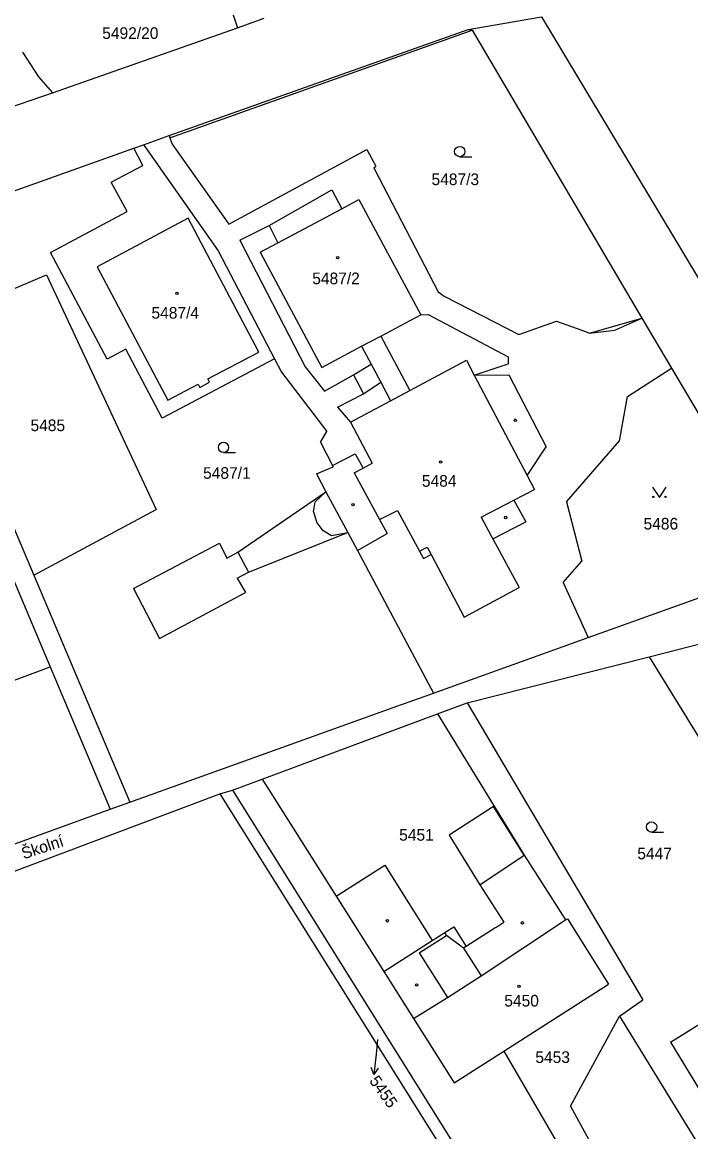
# Model space of a CAD drawing. Extents: x -717507 to -715515, y -957700 to -954941.
# Drawn here: x -716318.3 to -716220.6, y -955452.3 to -955290.3 of the extents above; entities that cross this region are included whole.
import ezdxf

# ---------------------------------------------------------------- set-up
doc = ezdxf.new("R2010")
doc.units = 0
for name, color, linetype in [('Hranice parcel', 7, 'Continuous'), ('Parcelní čísla', 7, 'Continuous'), ('Pop  PČ popisy', 7, 'Continuous'), ('Vnitřní kresba', 7, 'Continuous'), ('Značky budov', 7, 'Continuous'), ('Značky kultur', 7, 'Continuous')]:
    doc.layers.add(name, color=color, linetype=linetype)

msp = doc.modelspace()

# ---------------------------------------------------------------- linework, layer by layer
at = {"layer": 'Hranice parcel'}
for points in [[(-716253.14, -955291.32), (-716242.42, -955289.49)], [(-716242.42, -955289.49), (-716201.66, -955357.42)], [(-716313.88, -955300.58), (-716286.81, -955291.09)], [(-716286.81, -955291.09), (-716282.92, -955289.68)], [(-716296.83, -955306.84), (-716253.14, -955291.32)], [(-716253.14, -955291.32), (-716252.56, -955291.46)], [(-716252.56, -955291.46), (-716227.73, -955333.49)], [(-716318.24, -955294.63), (-716315.92, -955298.25)], [(-716315.92, -955298.25), (-716313.88, -955300.58)], [(-716320.4, -955302.84), (-716313.88, -955300.58)], [(-716300.57, -955308.17), (-716296.83, -955306.84)], [(-716296.83, -955306.84), (-716296.71, -955307.15)], [(-716296.71, -955307.15), (-716296.37, -955308.09)], [(-716337.65, -955321.38), (-716302, -955308.68)], [(-716302, -955308.68), (-716300.57, -955308.17)], [(-716300.67, -955311.21), (-716302, -955308.68)], [(-716300.57, -955308.17), (-716300.38, -955308.43)], [(-716300.38, -955308.43), (-716289.68, -955323.69)], [(-716296.37, -955308.09), (-716288.11, -955319.76)], [(-716288.11, -955319.76), (-716267.94, -955308.86)], [(-716267.94, -955308.86), (-716266.61, -955311.32)], [(-716305.28, -955313.62), (-716300.67, -955311.21)], [(-716266.92, -955311.56), (-716266.61, -955311.32)], [(-716266.92, -955311.56), (-716257.49, -955329.66)], [(-716302.97, -955317.94), (-716305.28, -955313.62)], [(-716282.22, -955319.95), (-716273.05, -955314.77)], [(-716273.05, -955314.77), (-716271.58, -955317.52)], [(-716271.58, -955317.52), (-716269.09, -955316.19)], [(-716269.09, -955316.19), (-716260.05, -955333.01)], [(-716314.14, -955323.91), (-716302.97, -955317.94)], [(-716282.22, -955319.95), (-716280.94, -955322.51)], [(-716283.5, -955323.87), (-716280.94, -955322.51)], [(-716305.87, -955339.49), (-716314.14, -955323.91)], [(-716289.68, -955323.69), (-716281.41, -955339.42)], [(-716283.5, -955323.87), (-716274.53, -955340.71)], [(-716332.07, -955334.52), (-716314.74, -955327.19)], [(-716314.74, -955327.19), (-716298.71, -955361.45)], [(-716337.22, -955329.83), (-716314.22, -955384.44)], [(-716257.49, -955329.66), (-716256.65, -955330.3)], [(-716256.65, -955330.3), (-716245.71, -955335.87)], [(-716265.88, -955336.12), (-716260.05, -955333.01)], [(-716332.07, -955334.52), (-716316.6, -955371.03)], [(-716245.71, -955335.87), (-716240.24, -955333.92)], [(-716240.24, -955333.92), (-716235.96, -955335.46)], [(-716235.39, -955335.67), (-716227.73, -955333.49)], [(-716227.73, -955333.49), (-716223.4, -955340.81)], [(-716265.88, -955336.12), (-716261.65, -955344.05)], [(-716235.96, -955335.46), (-716235.39, -955335.67)], [(-716303.16, -955338.02), (-716305.87, -955339.49)], [(-716297.84, -955348.12), (-716303.16, -955338.02)], [(-716274.53, -955340.71), (-716268.69, -955337.6)], [(-716268.69, -955337.6), (-716267.3, -955340.22)], [(-716281.41, -955339.42), (-716297.84, -955348.12)], [(-716281.41, -955339.42), (-716280.38, -955341.37)], [(-716280.38, -955341.37), (-716273.79, -955350.05)], [(-716269.88, -955341.77), (-716267.3, -955340.22)], [(-716229.86, -955344.96), (-716223.4, -955340.81)], [(-716223.4, -955340.81), (-716206.48, -955369.38)], [(-716269.88, -955341.77), (-716268.41, -955344.55)], [(-716268.41, -955344.55), (-716265.89, -955342.86)], [(-716265.89, -955342.86), (-716264.46, -955345.55)], [(-716264.46, -955345.55), (-716261.65, -955344.05)], [(-716231.03, -955351.43), (-716229.86, -955344.96)], [(-716274.7, -955351.62), (-716273.79, -955350.05)], [(-716274.7, -955351.62), (-716272.96, -955355)], [(-716238.78, -955360.31), (-716231.03, -955351.43)], [(-716275.31, -955356.21), (-716272.86, -955355.2)], [(-716272.96, -955355), (-716272.86, -955355.2)], [(-716275.31, -955356.21), (-716273.9, -955358.84)], [(-716273.9, -955358.84), (-716270.7, -955364.8)], [(-716238.78, -955360.31), (-716236.52, -955368.98)], [(-716316.6, -955371.03), (-716298.71, -955361.45)], [(-716270.7, -955364.8), (-716269.3, -955367.41)], [(-716269.3, -955367.41), (-716258.17, -955388.25)], [(-716239.26, -955372.11), (-716236.52, -955368.98)], [(-716235.59, -955380.15), (-716206.92, -955369.86)], [(-716316.6, -955371.03), (-716302.55, -955404.17)], [(-716239.26, -955372.11), (-716235.59, -955380.15)], [(-716258.17, -955388.25), (-716235.59, -955380.15)], [(-716226.67, -955382.96), (-716216.99, -955380.47)], [(-716253.26, -955389.67), (-716226.67, -955382.96)], [(-716226.67, -955382.96), (-716214.41, -955402.85)], [(-716323.52, -955387.9), (-716314.22, -955384.44)], [(-716314.22, -955384.44), (-716305.46, -955405.23)], [(-716302.55, -955404.17), (-716262.89, -955389.94), (-716262.42, -955389.77), (-716258.17, -955388.25)], [(-716257.61, -955391.29), (-716253.26, -955389.67)], [(-716253.26, -955389.67), (-716227.6, -955433.07)], [(-716283.22, -955400.82), (-716257.61, -955391.29)], [(-716257.61, -955391.29), (-716244.92, -955411.93)], [(-716287.58, -955402.44), (-716283.22, -955400.82)], [(-716283.22, -955400.82), (-716272.41, -955417.9)], [(-716377.69, -955436.18), (-716289.42, -955402.98)], [(-716289.42, -955402.98), (-716287.58, -955402.44)], [(-716289.42, -955402.98), (-716241.77, -955479.02)], [(-716287.58, -955402.44), (-716240.1, -955478.29)], [(-716305.46, -955405.23), (-716302.55, -955404.17)], [(-716352.74, -955422.37), (-716305.46, -955405.23)], [(-716249.42, -955404.8), (-716255.9, -955408.99)], [(-716244.92, -955411.93), (-716249.42, -955404.8)], [(-716255.9, -955408.99), (-716251.42, -955416.24)], [(-716244.92, -955411.93), (-716238.92, -955421.38)], [(-716272.41, -955417.9), (-716265.31, -955413.4)], [(-716265.31, -955413.4), (-716258.39, -955424.39)], [(-716251.42, -955416.24), (-716247.9, -955421.73)], [(-716272.41, -955417.9), (-716265.46, -955428.9)], [(-716256.55, -955423.22), (-716255.22, -955422.38)], [(-716255.22, -955422.38), (-716253.4, -955425.24)], [(-716249.07, -955422.47), (-716253.4, -955425.24)], [(-716249.07, -955422.47), (-716247.9, -955421.73)], [(-716238.92, -955421.38), (-716238.62, -955421.22)], [(-716238.62, -955421.22), (-716232.61, -955430.75)], [(-716258.39, -955424.39), (-716256.55, -955423.22)], [(-716223.55, -955439.22), (-716200.73, -955425.01)], [(-716265.46, -955428.9), (-716261.1, -955435.78)], [(-716247.93, -955440.53), (-716232.61, -955430.75)], [(-716231.01, -955435.42), (-716227.6, -955433.07)], [(-716238.19, -955448.6), (-716231.01, -955435.42)], [(-716231.01, -955435.42), (-716209.62, -955470.24)], [(-716261.1, -955435.78), (-716255.18, -955445.16)], [(-716223.55, -955439.22), (-716210.47, -955460.73)], [(-716255.18, -955445.16), (-716247.93, -955440.53)], [(-716247.93, -955440.53), (-716227.06, -955476.37)], [(-716238.19, -955448.6), (-716223.66, -955475.17)]]:
    msp.add_lwpolyline(points, dxfattribs=at)
at = {"layer": 'Pop  PČ popisy'}
for points in [[(-716266.36, -955438.83), (-716266.58, -955440.98)], [(-716266.58, -955440.98), (-716266.89, -955443.96)], [(-716266.29, -955443.02), (-716266.89, -955443.96), (-716267.28, -955442.92)]]:
    msp.add_lwpolyline(points, dxfattribs=at)
at = {"layer": 'Vnitřní kresba'}
for points in [[(-716290.79, -955279.43), (-716286.81, -955291.09)], [(-716296.71, -955307.15), (-716252.56, -955291.46)], [(-716280.94, -955322.51), (-716271.58, -955317.52)], [(-716294.04, -955318.91), (-716307.32, -955326)], [(-716283.72, -955338.45), (-716294.04, -955318.91)], [(-716286.5, -955322.12), (-716282.22, -955319.95)], [(-716286.5, -955322.12), (-716276.94, -955340.6)], [(-716307.32, -955326), (-716297.02, -955345.48)], [(-716260.05, -955333.01), (-716258.96, -955332.98)], [(-716258.96, -955332.98), (-716247.29, -955339.14)], [(-716231.69, -955335.25), (-716227.73, -955333.49)], [(-716268.69, -955337.6), (-716265.88, -955336.12)], [(-716235.39, -955335.67), (-716231.69, -955335.25)], [(-716291.16, -955342.38), (-716283.72, -955338.45)], [(-716261.65, -955344.05), (-716253.39, -955339.64)], [(-716253.39, -955339.64), (-716252.23, -955341.83)], [(-716247.29, -955339.14), (-716247.29, -955340.16)], [(-716276.94, -955340.6), (-716274.1, -955344.16)], [(-716267.3, -955340.22), (-716265.89, -955342.86)], [(-716252.23, -955341.83), (-716247.29, -955340.16)], [(-716292.34, -955343.61), (-716290.91, -955342.85)], [(-716290.91, -955342.85), (-716291.16, -955342.38)], [(-716274.1, -955344.16), (-716269.88, -955341.77)], [(-716252.23, -955341.83), (-716247.19, -955341.76)], [(-716252.23, -955341.83), (-716244.51, -955356.47)], [(-716247.19, -955341.76), (-716241.74, -955352.28)], [(-716297.02, -955345.48), (-716292.59, -955343.14)], [(-716292.59, -955343.14), (-716292.34, -955343.61)], [(-716272.23, -955346.52), (-716268.41, -955344.55)], [(-716270.32, -955348.67), (-716264.46, -955345.55)], [(-716272.23, -955346.52), (-716270.32, -955348.67)], [(-716270.32, -955348.67), (-716267.14, -955354.68)], [(-716244.51, -955356.47), (-716241.74, -955352.28)], [(-716272.96, -955355), (-716269.65, -955353.29)], [(-716269.65, -955353.29), (-716268.47, -955355.39)], [(-716269.76, -955356.07), (-716268.47, -955355.39)], [(-716268.47, -955355.39), (-716267.14, -955354.68)], [(-716269.76, -955356.07), (-716266.08, -955362.92)], [(-716244.51, -955356.47), (-716243.44, -955358.5)], [(-716286.77, -955367.68), (-716273.9, -955358.84)], [(-716275.48, -955360.31), (-716273.9, -955358.84)], [(-716246.45, -955360.07), (-716243.44, -955358.5)], [(-716275.73, -955361.8), (-716275.48, -955360.31)], [(-716251.23, -955362.58), (-716246.45, -955360.07)], [(-716246.45, -955360.07), (-716244.68, -955363.26)], [(-716275.73, -955361.8), (-716275.26, -955363.4)], [(-716266.08, -955362.92), (-716263.46, -955361.57)], [(-716263.46, -955361.57), (-716260.26, -955367.54)], [(-716275.26, -955363.4), (-716274.45, -955364.43)], [(-716266.08, -955362.92), (-716264.98, -955364.97)], [(-716251.23, -955362.58), (-716249.7, -955365.4)], [(-716249.51, -955365.75), (-716244.68, -955363.26)], [(-716285.24, -955370.6), (-716270.7, -955364.8)], [(-716274.45, -955364.43), (-716273.09, -955365.25)], [(-716273.09, -955365.25), (-716270.7, -955364.8)], [(-716269.3, -955367.41), (-716264.98, -955364.97)], [(-716249.7, -955365.4), (-716249.51, -955365.75)], [(-716249.51, -955365.75), (-716245.66, -955372.84)], [(-716302.05, -955372.98), (-716289.47, -955366.35)], [(-716289.47, -955366.35), (-716288.39, -955368.53)], [(-716260.26, -955367.54), (-716259.12, -955366.95)], [(-716259.12, -955366.95), (-716258.55, -955368.02)], [(-716288.39, -955368.53), (-716286.77, -955367.68)], [(-716286.77, -955367.68), (-716285.24, -955370.6)], [(-716260.26, -955367.54), (-716259.66, -955368.6)], [(-716259.66, -955368.6), (-716258.55, -955368.02)], [(-716258.55, -955368.02), (-716253.71, -955377.16)], [(-716286.86, -955371.45), (-716285.24, -955370.6)], [(-716286.86, -955371.45), (-716285.67, -955373.58)], [(-716302.05, -955372.98), (-716298.23, -955380.28)], [(-716298.23, -955380.28), (-716285.67, -955373.58)], [(-716253.71, -955377.16), (-716245.66, -955372.84)], [(-716251.42, -955416.24), (-716244.92, -955411.93)], [(-716251.23, -955429.57), (-716238.92, -955421.38)], [(-716260.3, -955426.2), (-716256.27, -955423.65)], [(-716256.27, -955423.65), (-716256.55, -955423.22)], [(-716253.82, -955425.51), (-716256.27, -955423.65)], [(-716265.46, -955428.9), (-716258.39, -955424.39)], [(-716253.4, -955425.24), (-716253.82, -955425.51)], [(-716253.82, -955425.51), (-716251.23, -955429.57)], [(-716260.3, -955426.2), (-716256.13, -955432.71)], [(-716256.13, -955432.71), (-716251.23, -955429.57)], [(-716261.1, -955435.78), (-716256.13, -955432.71)]]:
    msp.add_lwpolyline(points, dxfattribs=at)
at = {"layer": 'Značky budov'}
for centre in [(-716272.18, -955324.66), (-716295.69, -955329.87), (-716246.25, -955348.4), (-716257.16, -955354.52), (-716269.96, -955360.75), (-716247.64, -955362.61), (-716264.93, -955421.51), (-716245.2, -955421.81), (-716260.66, -955430.87), (-716245.71, -955431.08)]:
    msp.add_circle(centre, 0.175, dxfattribs=at)
at = {"layer": 'Značky kultur'}
for points in [[(-716254.36, -955309.92), (-716252.61, -955309.92)], [(-716288.88, -955353.12), (-716287.13, -955353.12)], [(-716226.19, -955358.2), (-716225.19, -955359.7), (-716224.19, -955358.2)], [(-716226.32, -955408.56), (-716224.57, -955408.56)]]:
    msp.add_lwpolyline(points, dxfattribs=at)
for centre, radius in [((-716254.36, -955309.17), 0.75), ((-716288.88, -955352.37), 0.75), ((-716226.09, -955359.6), 0.1), ((-716224.29, -955359.6), 0.1), ((-716226.32, -955407.81), 0.75)]:
    msp.add_circle(centre, radius, dxfattribs=at)

# ---------------------------------------------------------------- texts
at = {"layer": 'Parcelní čísla'}
for s, p in [('5492/20', (-716306.6, -955292.72)), ('5487/3', (-716258.48, -955314.07)), ('5487/2', (-716275.91, -955328.54)), ('5487/4', (-716299.4, -955333.57)), ('5485', (-716317.08, -955350)), ('5487/1', (-716291.86, -955356.96)), ('5484', (-716259.89, -955358.12)), ('5486', (-716227.5, -955364.37)), ('5451', (-716263.21, -955409.81)), ('5447', (-716228.41, -955412.52)), ('5450', (-716247.85, -955434.03)), ('5453', (-716243.31, -955442.27))]:
    msp.add_text(s, height=1.7, dxfattribs=at).set_placement(p)
msp.add_text('5455', height=1.7, rotation=305.4024, dxfattribs=at).set_placement((-716267.64, -955444.89))
at = {"layer": 'Pop  PČ popisy'}
msp.add_text('Školní', height=1.7, rotation=18.3001, dxfattribs=at).set_placement((-716318.07, -955412.54))

doc.saveas('drawing.dxf')
